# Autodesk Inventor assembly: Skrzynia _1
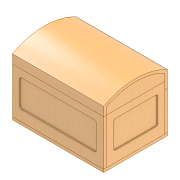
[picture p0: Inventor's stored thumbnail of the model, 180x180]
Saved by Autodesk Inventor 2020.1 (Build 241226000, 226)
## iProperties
Manager: www.cadconsulting.pl
Company: Fabian Stasiak CAD Consulting
Created: 2019-06
Part Number: Skrzynia _1
Document SubType Name: Assembly
Designer: F.Stasiak
Author: F.Stasiak
Subject: Zbiór ćwiczeń. Autodesk Inventor 2020. Kurs podstawowy
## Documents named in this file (6)
- C:\2020_Kurs_podstawowy\R6 Zespoły\Wiązania\Skrzynia I\Skrzynia _1.iam
- C:\2020_Kurs_podstawowy\R6 Zespoły\Wiązania\Skrzynia I\Spód.ipt
- C:\2020_Kurs_podstawowy\R6 Zespoły\Wiązania\Skrzynia I\Bok długi.ipt
- C:\2020_Kurs_podstawowy\R6 Zespoły\Wiązania\Skrzynia I\Bok krótki.ipt
- C:\2020_Kurs_podstawowy\R6 Zespoły\Wiązania\Skrzynia I\Wieko_1.iam
- C:\2020_Kurs_podstawowy\R6 Zespoły\Wiązania\Skrzynia I\Bok niski_1.ipt
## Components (6 placed, 5 different names)
1. Spód:1 — Zestawiające:1, Równoległe:1, Równoległe:2, Zestawiające:2, Równoległe:3, Zestawiające:4, Równoległe:4, Zestawiające:8
2. Bok długi:1 — Zestawiające:1, Równoległe:1, Równoległe:2, Zestawiające:3, Zestawiające:5, Równoległe:8
3. Bok krótki:1 — Zestawiające:4, Równoległe:4, Zestawiające:5, Równoległe:6
4. Bok krótki:2 — Zestawiające:2, Równoległe:3, Zestawiające:3, Równoległe:7, Zestawiające:9, Równoległe:9
5. Bok niski_1:1 — Równoległe:6, Zestawiające:8, Równoległe:7
6. Wieko_1:1 [sub-assembly] — Zestawiające:9, Równoległe:8, Równoległe:9
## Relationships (15: Flush 8, Mate 7)
- Zestawiające:1 [Mate]: Spód:1 ↔ Bok długi:1
- Równoległe:1 [Flush]: Spód:1 ↔ Bok długi:1
- Równoległe:2 [Flush]: Spód:1 ↔ Bok długi:1
- Zestawiające:2 [Mate]: Spód:1 ↔ Bok krótki:2
- Równoległe:3 [Flush]: Spód:1 ↔ Bok krótki:2
- Zestawiające:3 [Mate]: Bok długi:1 ↔ Bok krótki:2
- Zestawiające:4 [Mate]: Spód:1 ↔ Bok krótki:1
- Równoległe:4 [Flush]: Spód:1 ↔ Bok krótki:1
- Zestawiające:5 [Mate]: Bok długi:1 ↔ Bok krótki:1
- Równoległe:6 [Flush]: Bok krótki:1 ↔ Bok niski_1:1
- Zestawiające:8 [Mate]: Spód:1 ↔ Bok niski_1:1
- Równoległe:7 [Flush]: Bok krótki:2 ↔ Bok niski_1:1
- Zestawiające:9 [Mate]: Bok krótki:2 ↔ Wieko_1:1
- Równoległe:8 [Flush]: Bok długi:1 ↔ Wieko_1:1
- Równoległe:9 [Flush]: Bok krótki:2 ↔ Wieko_1:1
